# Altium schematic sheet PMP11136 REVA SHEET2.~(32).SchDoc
size 431 x 279 mm; Date: Not shown in title block; ApprovedBy: Not shown in title block; CheckedBy: Not shown in title block; Author: Not shown in title block; CompanyName: Not shown in title block; Engineer: Not shown in title block; Organization: Not shown in title block; Address1: Not shown in title block; Address2: Not shown in title block; Address3: Not shown in title block; Address4: Not shown in title block; DocumentNumber: 2; Revision: Use project parameter SCH_Rev; SheetNumber: 2; SheetTotal: 3; PageSetup: Record=PageOptions¦CenterHorizontal=True¦CenterVertical=True¦PrintScale=1.00¦XCorrection=1.00¦YCorrection=1.00¦PrintKind=0¦BorderSize=5000000¦LeftOffset=0¦BottomOffset=0¦Orientation=2¦PaperLength=1000¦PaperWidth=1000¦Scale=100¦PaperSource=15¦PrintQuality=600¦MediaType=1¦DitherType=10¦PaperKind=Letter¦PrintScaleMode=1
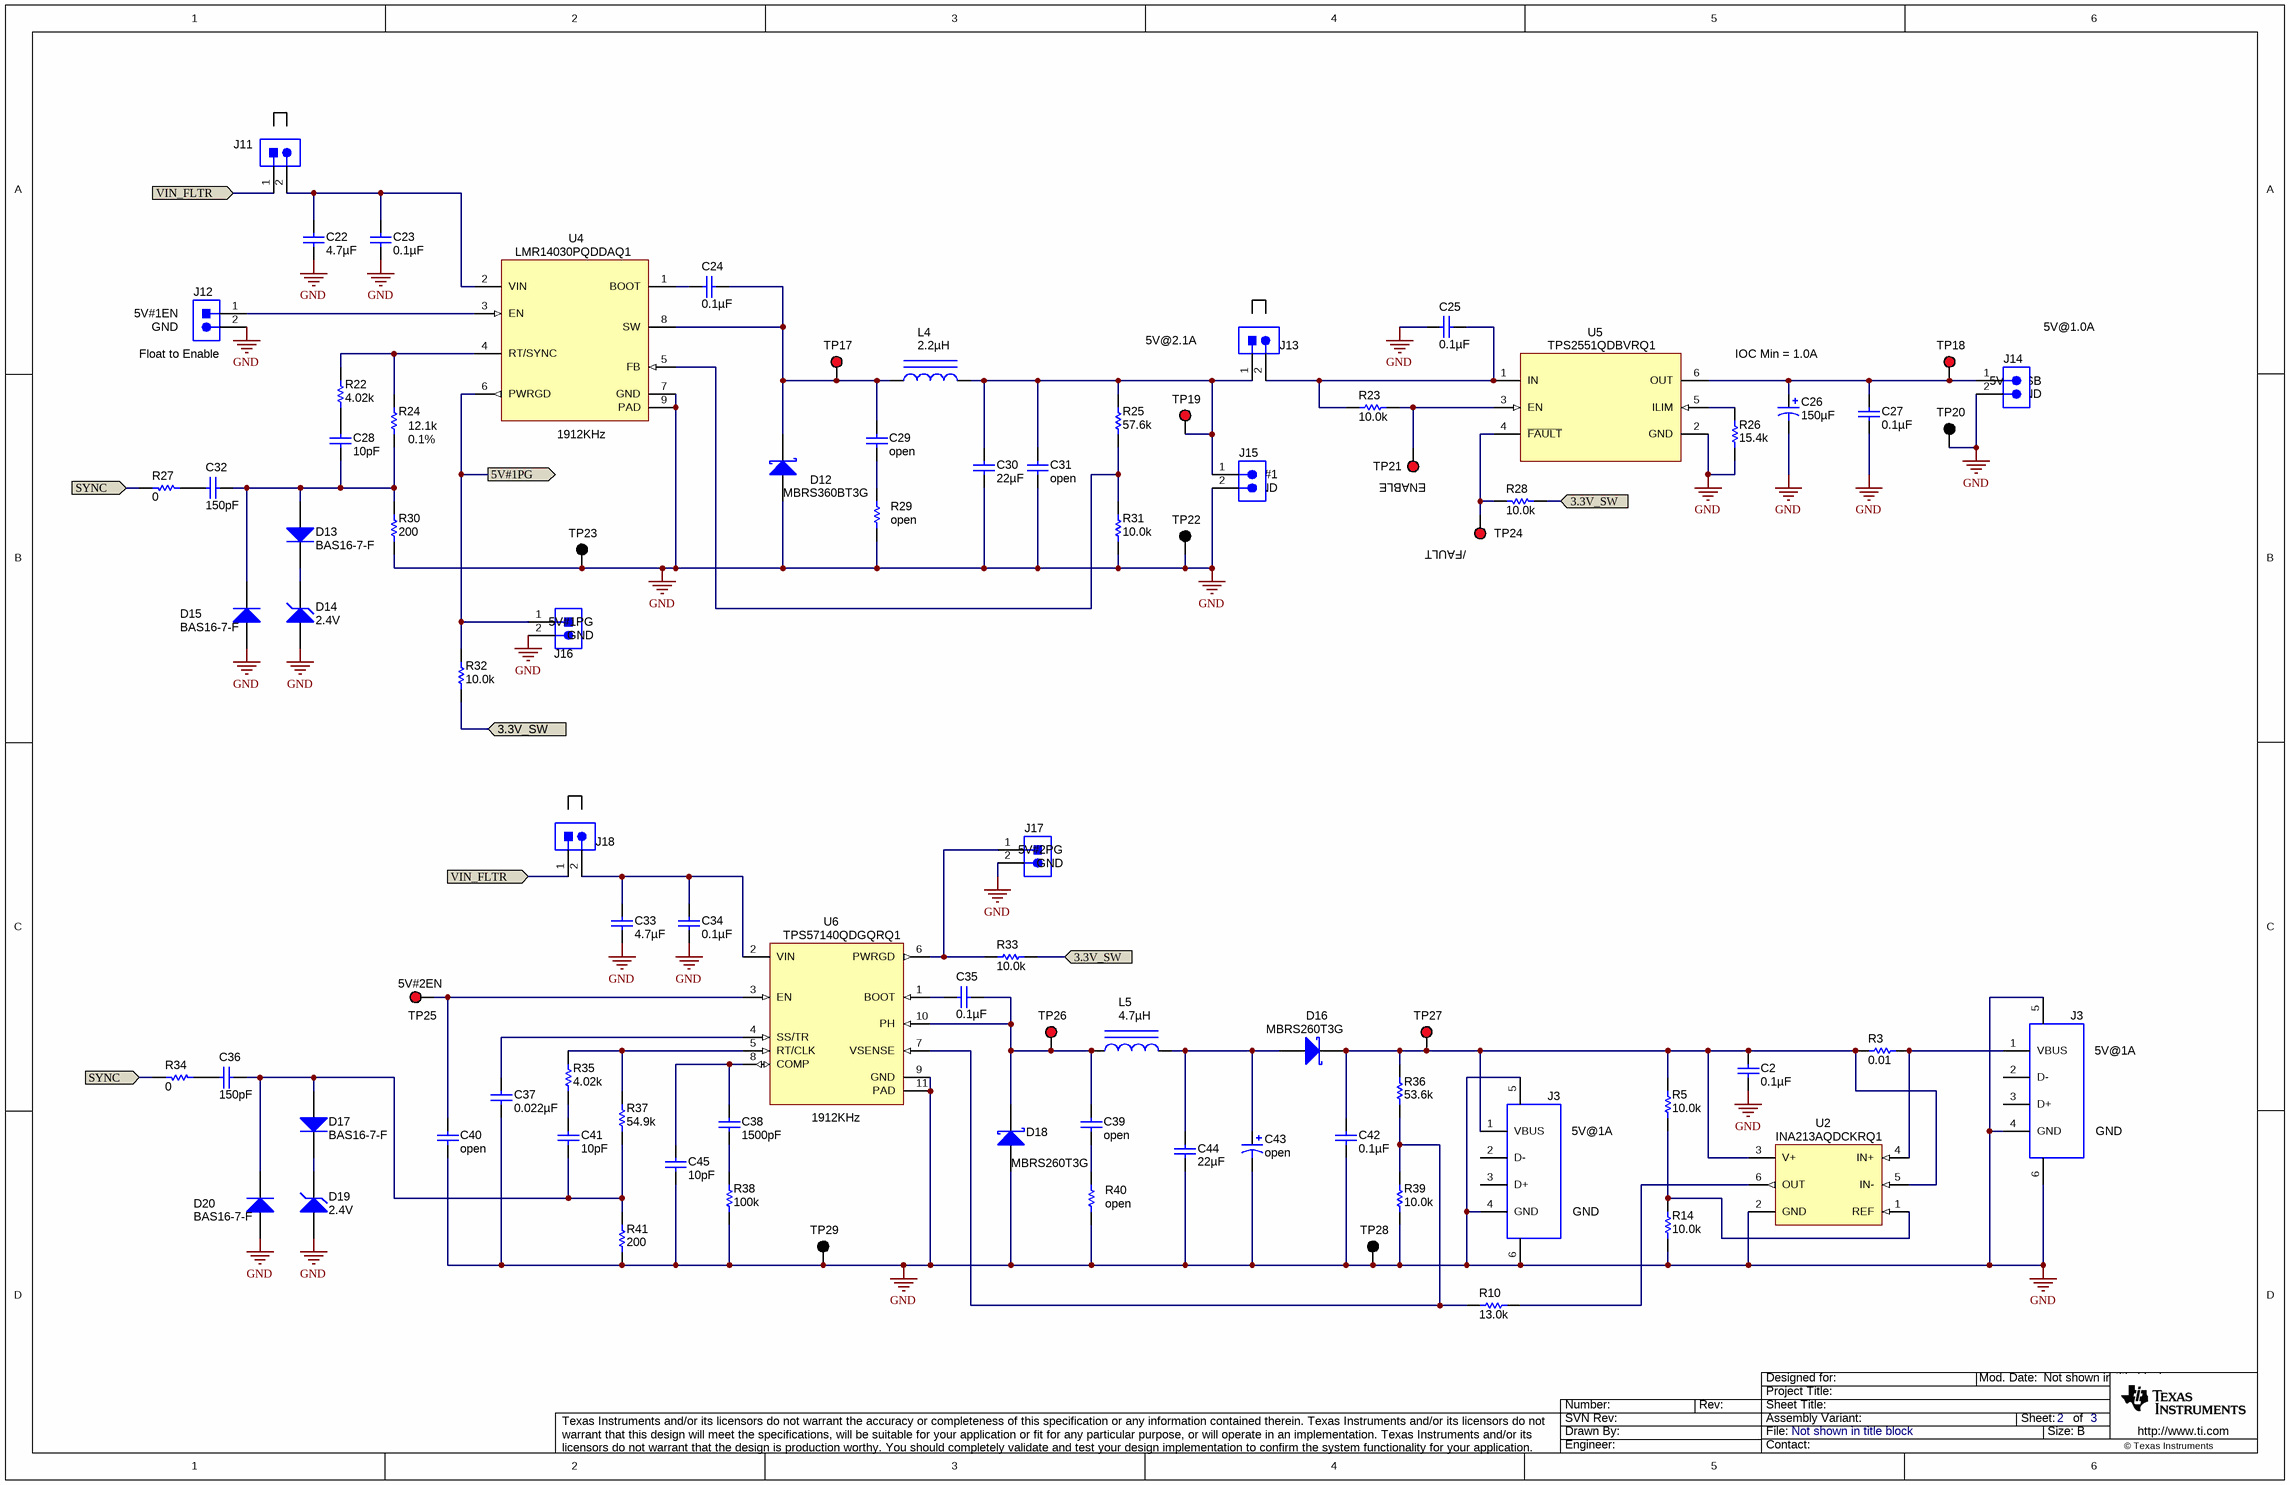
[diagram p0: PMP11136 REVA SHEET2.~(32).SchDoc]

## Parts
(Parts that share a designator on the sheet are numbered #1, #2 ... from top to bottom, then left to right.)
C2  ValueDisplayed: 0.1µF  [0402]  (hidden comment: C1005X7R1H104K050BB)
C22  ValueDisplayed: 4.7µF  [1210]  (hidden comment: C3225X7R1H475M250AB)
C23  ValueDisplayed: 0.1µF  [0603]  (hidden comment: C1608X7R1H104K)
C24  ValueDisplayed: 0.1µF  [0603]  (hidden comment: C1608X7R1H104K)
C25  ValueDisplayed: 0.1µF  [0603]  (hidden comment: C1608X7R1H104K)
C26  ValueDisplayed: 150µF  [TPB_D4]  (hidden comment: 10TPB150ML)
C27  ValueDisplayed: 0.1µF  [0603]  (hidden comment: C1608X7R1H104K)
C28  ValueDisplayed: 10pF  [0603]  (hidden comment: C1608C0G1H100D)
C29  ValueDisplayed: open  [0603]
C30  ValueDisplayed: 22µF  [1210]  (hidden comment: C3225X7R1C226M250AC)
C31  ValueDisplayed: open  [1210]
C32  ValueDisplayed: 150pF  [0603]  (hidden comment: C1608C0G1H151J)
C33  ValueDisplayed: 4.7µF  [1210]  (hidden comment: C3225X7R1H475M250AB)
C34  ValueDisplayed: 0.1µF  [0603]  (hidden comment: C1608X7R1H104K)
C35  ValueDisplayed: 0.1µF  [0603]  (hidden comment: C1608X7R1H104K)
C36  ValueDisplayed: 150pF  [0603]  (hidden comment: C1608C0G1H151J)
C37  ValueDisplayed: 0.022µF  [0603]  (hidden comment: C1608X7R1H223K)
C38  ValueDisplayed: 1500pF  [0603]  (hidden comment: C1608C0G1H152J)
C39  ValueDisplayed: open  [0603]
C40  ValueDisplayed: open  [0603]
C41  ValueDisplayed: 10pF  [0603]  (hidden comment: C1608C0G1H100D)
C42  ValueDisplayed: 0.1µF  [0603]  (hidden comment: C1608X7R1H104K)
C43  ValueDisplayed: open  [TPB_D4]
C44  ValueDisplayed: 22µF  [1210]  (hidden comment: C3225X7R1C226M250AC)
C45  ValueDisplayed: 10pF  [0603]  (hidden comment: C1608C0G1H100D)
D12  MBRS360BT3G  [SMB]
D13  BAS16-7-F  [SOT-23]
D14  value 2.4V  [SOD-123]  (hidden comment: MMSZ5221B-7-F)
D15  BAS16-7-F  [SOT-23]
D16  MBRS260T3G  [SMB]
D17  BAS16-7-F  [SOT-23]
D18  MBRS260T3G  [SMB]
D19  value 2.4V  [SOD-123]  (hidden comment: MMSZ5221B-7-F)
D20  BAS16-7-F  [SOT-23]
J3#1  676430910  [MOLEX_0676430910]  (value not drawn)
J3#2  676430910  [MOLEX_0676430910]  (value not drawn)
J11  PEC02SAAN  [CONN_PEC02SAAN]  (value not drawn)
J12  PEC02SAAN  [CONN_PEC02SAAN]  (value not drawn)
J13  PEC02SAAN  [CONN_PEC02SAAN]  (value not drawn)
J14  ED555/2DS  [TERM_BLK_ED555-2DS]  (value not drawn)
J15  ED555/2DS  [TERM_BLK_ED555-2DS]  (value not drawn)
J16  PEC02SAAN  [CONN_PEC02SAAN]  (value not drawn)
J17  PEC02SAAN  [CONN_PEC02SAAN]  (value not drawn)
J18  PEC02SAAN  [CONN_PEC02SAAN]  (value not drawn)
L4  ValueDisplayed: 2.2µH  [CLF6045NI-D]  (hidden comment: CLF6045NIT-2R2N-D)
L5  ValueDisplayed: 4.7µH  [CLF6045NI-D]  (hidden comment: CLF6045NIT-4R7N-D)
R3  value 0.01  [2512M]  (hidden comment: ERJ-M1WSF10MU)
R5  value 10.0k  [0402]  (hidden comment: CRCW040210K0FKED)
R10  value 13.0k  [0402]  (hidden comment: CRCW040213K0FKED)
R14  value 10.0k  [0402]  (hidden comment: CRCW040210K0FKED)
R22  ValueDisplayed: 4.02k  [0603]  (hidden comment: CRCW06034K02FKEA)
R23  ValueDisplayed: 10.0k  [0603]  (hidden comment: CRCW060310K0FKEA)
R24  Value1: 0.1%  ValueDisplayed: 12.1k  [0603]
R25  ValueDisplayed: 57.6k  [0603]  (hidden comment: CRCW060357K6FKEA)
R26  ValueDisplayed: 15.4k  [0603]  (hidden comment: CRCW060315K4FKEA)
R27  ValueDisplayed: 0  [0603]  (hidden comment: CRCW06030000Z0EA)
R28  ValueDisplayed: 10.0k  [0603]  (hidden comment: CRCW060310K0FKEA)
R29  value open  [2010]
R30  ValueDisplayed: 200  [0603]  (hidden comment: CRCW0603200RFKEA)
R31  ValueDisplayed: 10.0k  [0603]  (hidden comment: CRCW060310K0FKEA)
R32  ValueDisplayed: 10.0k  [0603]  (hidden comment: CRCW060310K0FKEA)
R33  ValueDisplayed: 10.0k  [0603]  (hidden comment: CRCW060310K0FKEA)
R34  ValueDisplayed: 0  [0603]  (hidden comment: CRCW06030000Z0EA)
R35  ValueDisplayed: 4.02k  [0603]  (hidden comment: CRCW06034K02FKEA)
R36  ValueDisplayed: 53.6k  [0603]  (hidden comment: CRCW060353K6FKEA)
R37  ValueDisplayed: 54.9k  [0603]  (hidden comment: CRCW060354K9FKEA)
R38  ValueDisplayed: 100k  [0603]  (hidden comment: CRCW0603100KFKEA)
R39  ValueDisplayed: 10.0k  [0603]  (hidden comment: CRCW060310K0FKEA)
R40  value open  [2010]
R41  ValueDisplayed: 200  [0603]  (hidden comment: CRCW0603200RFKEA)
TP17  5000  [Keystone5000]  (value not drawn)
TP18  5000  [Keystone5000]  (value not drawn)
TP19  5000  [Keystone5000]  (value not drawn)
TP20  5001  [Keystone5001]  (value not drawn)
TP21  5000  [Keystone5000]  (value not drawn)
TP22  5001  [Keystone5001]  (value not drawn)
TP23  5001  [Keystone5001]  (value not drawn)
TP24  5000  [Keystone5000]  (value not drawn)
TP25  5000  [Keystone5000]  (value not drawn)
TP26  5000  [Keystone5000]  (value not drawn)
TP27  5000  [Keystone5000]  (value not drawn)
TP28  5001  [Keystone5001]  (value not drawn)
TP29  5001  [Keystone5001]  (value not drawn)
U2  INA213AQDCKRQ1  [DCK0006A_N]
U4  LMR14030PQDDAQ1  [DDA0008E_N]
U5  TPS2551QDBVRQ1  [DBV0006A_N]
U6  TPS57140QDGQRQ1  [DGQ0010D_N]

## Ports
3.3V_SW, 5V#1PG, SYNC, VIN_FLTR

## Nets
GND: C2.2 C22.1 C23.2 C25.1 C26.2(-) C27.1 C30.2 C31.2 C33.1 C34.2 C37.2 C40.2 C42.2 C43.2(-) C44.2 C45.2 D12.2(A) D14.2(A) D15.1(A) D18.2(A) D19.2(A) D20.1(A) J3#1.4(GND) J3#1.5(Shield) J3#1.6(Shield) J3#2.4(GND) J3#2.5(Shield) J3#2.6(Shield) J12.2 J14.2 J15.2 J16.2 J17.2 R14.1 R26.2 R29.1 R30.1 R31.1 R38.1 R39.1 R40.1 R41.1 TP20.1 TP22.1 TP23.1 TP28.1 TP29.1 U2.2(GND) U4.7(GND) U4.9(PAD) U5.2(GND) U6.9(GND) U6.11(PAD)
3.3V_SW: R28.2 R32.1 R33.1 ; port 3.3V_SW
5V#1PG: J16.1 R32.2 U4.6(PWRGD) ; port 5V#1PG
SYNC: R27.1 R34.1 ; port SYNC
VIN_FLTR: J11.1 J18.1 ; port VIN_FLTR
NetC2_1: C2.1 C42.1 D16.1(K) J3#2.1(VBUS) R3.1 R5.2 R36.2 TP27.1 U2.3(V+) U2.5(IN-)
NetC22_2: C22.2 C23.1 J11.2 U4.2(VIN)
NetC24_1: C24.1 U4.1(BOOT)
NetC24_2: C24.2 C29.1 D12.1(K) L4.1 TP17.1 U4.8(SW)
NetC25_2: C25.2 J13.2 R23.2 U5.1(IN)
NetC26_1: C26.1(+) C27.2 J14.1 TP18.1 U5.6(OUT)
NetC28_1: C28.1 R22.2
NetC28_2: C28.2 C32.1 D13.1(A) D15.3(K) R24.1 R30.2
NetC29_2: C29.2 R29.2
NetC30_1: C30.1 C31.1 J13.1 J15.1 L4.2 R25.2 TP19.1
NetC32_2: C32.2 R27.2
NetC33_2: C33.2 C34.1 J18.2 U6.2(VIN)
NetC35_1: C35.1 U6.1(BOOT)
NetC35_2: C35.2 C39.1 D18.1(K) L5.1 TP26.1 U6.10(PH)
NetC36_1: C36.1 C41.2 D17.1(A) D20.3(K) R37.1 R41.2
NetC36_2: C36.2 R34.2
NetC37_1: C37.1 U6.4(SS/TR)
NetC38_1: C38.1 C45.1 U6.8(COMP)
NetC38_2: C38.2 R38.2
NetC39_2: C39.2 R40.2
NetC40_1: C40.1 TP25.1 U6.3(EN)
NetC41_1: C41.1 R35.2
NetC43_1: C43.1(+) C44.1 D16.2(A) L5.2
NetD13_3: D13.3(K) D14.1(K)
NetD17_3: D17.3(K) D19.1(K)
NetJ3#1_1: J3#1.1(VBUS) R3.2 U2.4(IN+)
NetJ12_1: J12.1 U4.3(EN)
NetJ17_1: J17.1 R33.2 U6.6(PWRGD)
NetR5_1: R5.1 R14.2 U2.1(REF)
NetR10_1: R10.1 U2.6(OUT)
NetR10_2: R10.2 R36.1 R39.2 U6.7(VSENSE)
NetR22_1: R22.1 R24.2 U4.4(RT/SYNC)
NetR23_1: R23.1 TP21.1 U5.3(EN)
NetR25_1: R25.1 R31.2 U4.5(FB)
NetR26_1: R26.1 U5.5(ILIM)
NetR28_1: R28.1 TP24.1 U5.4(~{FAULT})
NetR35_1: R35.1 R37.2 U6.5(RT/CLK)

Not connected (* = marked no-connect by the designer): J3#1 2(D-) 3(D+); J3#2 2(D-) 3(D+)

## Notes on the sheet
- (near J12) 5V#1EN
- (near J12) GND
- (near J12) Float to Enable
- 5V@2.1A
- IOC Min = 1.0A
- 5V@1.0A
- (near U4) 1912KHz
- (near J14) 5V#1USB
- (near J14) GND
- (near J15) 5V#1
- (near J15) GND
- (near TP21) ENABLE
- (near TP24) /FAULT
- 5V#1PG
- (near J16) GND
- (near J17) 5V#2PG
- (near J17) GND
- (near TP25) 5V#2EN
- 5V@1A
- (near U6) 1912KHz
- GND

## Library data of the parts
C2 = C1005X7R1H104K050BB: CAP, CERM, 0.1uF, 50V, +/-10%, X7R, 0402; Manufacturer: TDK; Polarized: N; CompType: Capacitor; U/M: EA; Cap_F: 0.0000001; Tolerance_%: 10; Value1: Unknown; VDC_V: 50; TaMin_C: -55; TaMax_C: 125
C22 C33 = C3225X7R1E106M: CAP, CERM, 4.7uF, 50V, +/-20%, X7R, 1210; Manufacturer: TDK; Polarized: N; CompType: Capacitor; U/M: EA; Cap_F: 0.00001; Tolerance_%: 20; ESR_Ohm: 0.0027; Value1: 0.0027 ohm; VDC_V: 50; IRMS_A: 3; TaMin_C: -55; TaMax_C: 125
C23-C25 C27 C34 C35 C42 = C1608X7R1H104K: CAP, CERM, 0.1uF, 50V, +/-10%, X7R, 0603; Manufacturer: TDK; Polarized: N; CompType: Capacitor; U/M: EA; Cap_F: 0.0000001; Tolerance_%: 10; ESR_Ohm: 0.017; Value1: 0.017 ohm; VDC_V: 50; TaMin_C: -55; TaMax_C: 125
C26 = 10TPB220M: CAP, 150uF, 10V, +/-20%, 0.04 ohm, SMD; Manufacturer: Panasonic; Polarized: Y; CompType: Capacitor; U/M: EA; Cap_F: 0.00022; Tolerance_%: 20; VDC_V: 10; ESR_Ohm: 0.04; IRMS_A: 3; TaMin_C: -55; TaMax_C: 105; Cap_Case: D
C28 C41 C45 = C1608C0G1H100D: CAP, CERM, 10 pF, 50 V, +/- 5%, C0G/NP0, 0603; Manufacturer: TDK; Polarized: N; CompType: Capacitor; Value: 10pF; U/M: EA; Cap_F: 0.00000000001; Tolerance_%: 5; ESR_ohm: 0.3492; Value1: 0.3492 ohm; VDC_V: 50; Value2: 50V; TaMin_C: -55; TaMax_C: 125
C29 C39 C40 = C1608C0G1H102J: CAP, CERM, open, 0603; Polarized: N; CompType: Capacitor; U/M: EA; Cap_F: 0.000000001; Tolerance_%: 5; ESR_ohm: 0.0563; TempCo: C0G/NP0; TaMin_C: -55; TaMax_C: 125
C30 C44 = C3225X7R1C226M: CAP, CERM, 22 µF, 16 V, +/- 20%, X7R, 1210; Manufacturer: TDK; Polarized: N; CompType: Capacitor; Value: 22uF; U/M: EA; Cap_F: 0.000022; Tolerance_%: 20; ESR_ohm: 0.002; Value1: 0.002 ohm; VDC_V: 16; Value2: 16V; IRMS_A: 8.11; TaMin_C: -55; TaMax_C: 125
C31 = C3225X7R1C226M: CAP, open, 1210; Polarized: N; CompType: Capacitor; U/M: EA; Cap_F: 0.000022; Tolerance_%: 20; ESR_ohm: 0.002; TempCo: X7R; IRMS_A: 8.11; TaMin_C: -55; TaMax_C: 125
C32 C36 = C1608C0G1H151J: CAP, CERM, 150 pF, 50 V, +/- 5%, C0G/NP0, 0603; Manufacturer: TDK; Polarized: N; CompType: Capacitor; Value: 150pF; U/M: EA; Cap_F: 0.00000000015; Tolerance_%: 5; ESR_ohm: 0.1084; Value1: 0.1084 ohm; VDC_V: 50; Value2: 50V; TaMin_C: -55; TaMax_C: 125
C37 = C1608X7R1H223K: CAP, CERM, 0.022 µF, 50 V, +/- 10%, X7R, 0603; Manufacturer: TDK; Polarized: N; CompType: Capacitor; Value: 0.022uF; U/M: EA; Cap_F: 0.000000022; Tolerance_%: 10; ESR_ohm: 0.0383; Value1: 0.0383 ohm; VDC_V: 50; Value2: 50V; TaMin_C: -55; TaMax_C: 125
C38 = C1608C0G1H152J: CAP, CERM, 1500 pF, 50 V, +/- 5%, C0G/NP0, 0603; Manufacturer: TDK; Polarized: N; CompType: Capacitor; Value: 1500pF; U/M: EA; Cap_F: 0.0000000015; Tolerance_%: 5; ESR_ohm: 0.039; Value1: 0.039 ohm; VDC_V: 50; Value2: 50V; TaMin_C: -55; TaMax_C: 125
C43 = 10TPB220M: CAP, open, SMD; Polarized: Y; CompType: Capacitor; Value: 150uF; U/M: EA; Cap_F: 0.00022; Tolerance_%: 20; ESR_Ohm: 0.04; IRMS_A: 3; TaMin_C: -55; TaMax_C: 105; Cap_Case: D
D12 = MBRS260T3G: Diode, Schottky, 60V, 3A, SMB; Manufacturer: ON Semiconductor; U/M: EA; Vf_V: 0.63; Value2: 0.63V; Io_A: 2; Vr_V: 60; TJmax_C: 125; RJC_CperW: 24
D13 D15 D17 D20 = BAS16-7-F: Diode, Ultrafast, 75V, 0.3A, SOT-23; Manufacturer: Diodes Inc.; U/M: EA; Vf_V: 1.125; Value2: 1.125V; Io_A: 0.3; Vr_V: 75
D14 D19 = MMSZ5221B-7-F: Diode, Zener, 2.4V, 500 mW, SOD-123; Manufacturer: Diodes Inc.; SymbolCreator: a0412235; U/M: EA; Power_W: 0.5; Vz_V: 2.4; Value1: 0.5W; RJA_CperW: 350
D16 D18 = MBRS260T3G: Diode, Schottky, 60V, 2A, SMB; Manufacturer: ON Semiconductor; U/M: EA; Vf_V: 0.63; Value2: 0.63V; Io_A: 2; Vr_V: 60; TJmax_C: 125; RJC_CperW: 24
J3#1 J3#2 = 676430910: Connector, Receptacle, USB Standard, R/A, Top Mount TH; Manufacturer: Molex; SymbolCreator: a0412235; U/M: EA
J11-J13 J16-J18 = PEC02SAAN: Header, 100mil, 2x1, Tin, TH; Manufacturer: Sullins Connector Solutions; SymbolCreator: a0412235; U/M: EA
J14 J15 = ED555/2DS: Terminal Block, 6A, 3.5mm Pitch, 2-Pos, TH; Manufacturer: On-Shore Technology, Inc.; SymbolCreator: a0412235; CompType: Connector; U/M: EA
L4 = CLF6045NIT-2R2N-D: Inductor, Wirewound, Ferrite, 2.2 µH, 4.1 A, 0.015 ohm, SMD; Manufacturer: TDK; Value: 2.2uH; Ind_H: 2.2E-6; Imax_A: 4.1; Irms: 4.1A @ 40C rise; Isat: 4.2A @ 30% inductance drop; DCR_ohm: 0.015; Value2: 4.1A
L5 = CLF6045NIT-4R7N-D: Inductor, Wirewound, Ferrite, 4.7 µH, 3.1 A, 0.023 ohm, SMD; Manufacturer: TDK; Value: 4.7uH; Ind_H: 4.7E-6; Imax_A: 3.1; Irms: 3.3A @ 40C rise; Isat: 3.1A @ 30% inductance drop; DCR_ohm: 0.023; Value2: 3.1A
R3 = ERJ-M1WSF10MU: RES, 0.01 ohm, 1%, 1W, 2512; Manufacturer: Panasonic; CompType: Resistor; Value_Code: R010; Tolerance_%: 1; TempCo: 100 ppm/C; EIA_Code: E96; U/M: EA
R5 R14 = CRCW040210K0FKED: RES, 10.0k ohm, 1%, 0.063W, 0402; Manufacturer: Vishay-Dale; CompType: Resistor; Res_ohm: 10000; Value_Code: 10k0; Tolerance_%: 1; Power_W: 0.063; VDC_V: 50; TempCo: 100 ppm/C; EIA_Code: E96; U/M: EA
R10 = CRCW040213K0FKED: RES, 13.0k ohm, 1%, 0.063W, 0402; Manufacturer: Vishay-Dale; CompType: Resistor; Res_ohm: 13000; Value_Code: 13k0; Tolerance_%: 1; Power_W: 0.063; VDC_V: 50; TempCo: 100 ppm/C; EIA_Code: E96; U/M: EA
R22 R35 = CRCW06034K02FKEA: RES, 4.02 k, 1%, 0.1 W, 0603; Manufacturer: Vishay-Dale; CompType: Resistor; Value: 4.02k; Res_ohm: 4020; Value_Code: 4k02; Tolerance_%: 1; Power_W: 0.1; Value2: 0.1W; VDC_V: 75; TempCo: 100 ppm/C; EIA_Code: E96; U/M: EA
R23 R28 R31-R33 R39 = CRCW060310K0FKEA: RES, 10.0 k, 1%, 0.1 W, 0603; Manufacturer: Vishay-Dale; CompType: Resistor; Value: 10.0k; Res_ohm: 10000; Value_Code: 10k0; Tolerance_%: 1; Power_W: 0.1; Value2: 0.1W; VDC_V: 75; TempCo: 100 ppm/C; EIA_Code: E96; U/M: EA
R24 = CRCW060312K1FKEA: RES, 12.1 k, 0.1%, 0.1 W, 0603; Manufacturer: Vishay-Dale; CompType: Resistor; Value: 12.1k; Res_ohm: 12100; Value_Code: 12k1; Tolerance_%: 1; Power_W: 0.1; Value2: 0.1W; VDC_V: 75; TempCo: 100 ppm/C; EIA_Code: E96; U/M: EA
R25 = CRCW060357K6FKEA: RES, 57.6 k, 1%, 0.1 W, 0603; Manufacturer: Vishay-Dale; CompType: Resistor; Value: 57.6k; Res_ohm: 57600; Value_Code: 57k6; Tolerance_%: 1; Power_W: 0.1; Value2: 0.1W; VDC_V: 75; TempCo: 100 ppm/C; EIA_Code: E96; U/M: EA
R26 = CRCW060315K4FKEA: RES, 15.4 k, 1%, 0.1 W, 0603; Manufacturer: Vishay-Dale; CompType: Resistor; Value: 15.4k; Res_ohm: 15400; Value_Code: 15k4; Tolerance_%: 1; Power_W: 0.1; Value2: 0.1W; VDC_V: 75; TempCo: 100 ppm/C; EIA_Code: E96; U/M: EA
R27 R34 = CRCW06030000Z0EA: RES, 0, 5%, 0.1 W, 0603; Manufacturer: Vishay-Dale; CompType: Resistor; Value: 0; Value_Code: 0000; Tolerance_%: 5; Power_W: 0.1; Value2: 0.1W; VDC_V: 75; TempCo: 200 ppm/C; EIA_Code: E24; U/M: EA
R29 R40 = CRCW20102R70JNEF: RES, open, 2010; CompType: Resistor; Tolerance_%: 5; Power_W: 0.75; TempCo: 200 ppm/C; EIA_Code: E24; U/M: EA
R30 R41 = CRCW0603200RFKEA: RES, 200, 1%, 0.1 W, 0603; Manufacturer: Vishay-Dale; CompType: Resistor; Value: 200; Value_Code: 200R; Tolerance_%: 1; Power_W: 0.1; Value2: 0.1W; VDC_V: 75; TempCo: 100 ppm/C; EIA_Code: E96; U/M: EA
R36 = CRCW060353K6FKEA: RES, 53.6 k, 1%, 0.1 W, 0603; Manufacturer: Vishay-Dale; CompType: Resistor; Value: 53.6k; Res_ohm: 53600; Value_Code: 53k6; Tolerance_%: 1; Power_W: 0.1; Value2: 0.1W; VDC_V: 75; TempCo: 100 ppm/C; EIA_Code: E96; U/M: EA
R37 = CRCW060354K9FKEA: RES, 54.9 k, 1%, 0.1 W, 0603; Manufacturer: Vishay-Dale; CompType: Resistor; Value: 54.9k; Res_ohm: 54900; Value_Code: 54k9; Tolerance_%: 1; Power_W: 0.1; Value2: 0.1W; VDC_V: 75; TempCo: 100 ppm/C; EIA_Code: E96; U/M: EA
R38 = CRCW0603100KFKEA: RES, 100 k, 1%, 0.1 W, 0603; Manufacturer: Vishay-Dale; CompType: Resistor; Value: 100k; Res_ohm: 100000; Tolerance_%: 1; Power_W: 0.1; Value2: 0.1W; VDC_V: 75; TempCo: 100 ppm/C; EIA_Code: E96; U/M: EA
TP17-TP19 TP21 TP24-TP27 = 5000: Test Point, TH, Miniature, Red; Manufacturer: Keystone; CompType: Test Point Loop; U/M: EA
TP20 TP22 TP23 TP28 TP29 = 5001: Test Point, TH, Miniature, Black; Manufacturer: Keystone; CompType: Test Point Loop; U/M: EA
U2 = INA213AIDCK: Voltage Output, High or Low Side Measurement, Bi-Directional Zero-Drift Series Current-Shunt Monitor, DCK0006A; Alternate Manufacturer: None; Manufacturer: Texas Instruments; SymbolCreator: a0411947; CompType: IC; U/M: EA
U4 = LMR14030PDDAR: LMR14030PQDDAQ1, DDA0008E; Manufacturer: Texas Instruments; SymbolCreator: Altium; CompType: IC; U/M: EA
U5 = TPS2551QDBVRQ1: ADJUSTABLE CURRENT-LIMITED POWER-DISTRIBUTION SWITCH, DBV0006A; Manufacturer: Texas Instruments; SymbolCreator: Altium; CompType: IC; U/M: EA
U6 = TPS57140QDGQRQ1: 1.5-A 42-V STEP-DOWN SWIFT(TM) DC-DC CONVERTER WITH Eco-mode(TM) CONTROL, DGQ0010D; Alternate Manufacturer: None; Manufacturer: Texas Instruments; SymbolCreator: a0799628; CompType: IC; U/M: EA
